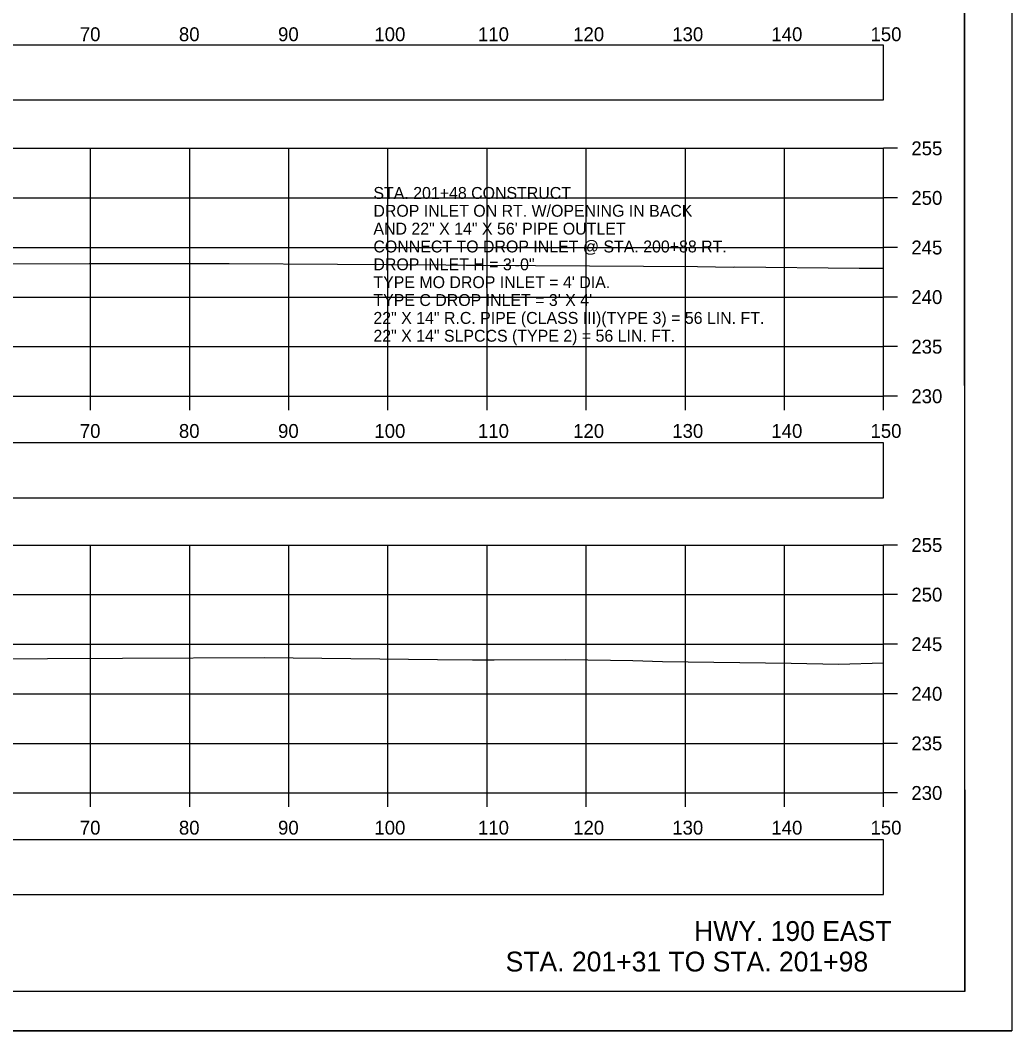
# Model space of a CAD drawing. Extents: x 1369627 to 1374022, y 380035 to 398173.
# Drawn here: x 1372161.4 to 1372261.5, y 380465.5 to 380567.3 of the extents above; entities that cross this region are included whole.
import ezdxf

# ---------------------------------------------------------------- set-up
doc = ezdxf.new("R2010")
doc.units = 0
for name, color, linetype in [('Default', 7, 'Continuous'), ('R_Axis', 7, 'Continuous'), ('R_Axis Annot', 7, 'Continuous'), ('R_Border', 7, 'Continuous'), ('R_Draft', 7, 'Continuous'), ('R_Exist Surface', 7, 'Continuous'), ('R_Grid', 7, 'Continuous'), ('R_No Plot', 7, 'Continuous'), ('R_Water Annot', 7, 'Continuous')]:
    doc.layers.add(name, color=color, linetype=linetype)

msp = doc.modelspace()

# ---------------------------------------------------------------- linework, layer by layer
at = {"layer": 'Default'}
for points in [[(1371948.53, 380559.31), (1372248.53, 380559.31), (1372248.53, 380564.83), (1371948.53, 380564.83)], [(1371948.53, 380519.2), (1372248.53, 380519.2), (1372248.53, 380524.73), (1371948.53, 380524.73)], [(1371948.53, 380479.19), (1372248.53, 380479.19), (1372248.53, 380484.71), (1371948.53, 380484.71)]]:
    msp.add_lwpolyline(points, close=True, dxfattribs=at)
at = {"layer": 'R_Axis'}
for p, q in [((1372248.53, 380529.43), (1372248.53, 380554.43)), ((1372249.93, 380554.43), (1372248.53, 380554.43)), ((1372249.93, 380549.43), (1372248.53, 380549.43)), ((1372249.93, 380544.43), (1372248.53, 380544.43)), ((1372249.93, 380539.43), (1372248.53, 380539.43)), ((1372249.93, 380534.43), (1372248.53, 380534.43)), ((1371948.53, 380529.43), (1372248.53, 380529.43)), ((1372168.53, 380528.03), (1372168.53, 380529.43)), ((1372178.53, 380528.03), (1372178.53, 380529.43)), ((1372188.53, 380528.03), (1372188.53, 380529.43)), ((1372198.53, 380528.03), (1372198.53, 380529.43)), ((1372208.53, 380528.03), (1372208.53, 380529.43)), ((1372218.53, 380528.03), (1372218.53, 380529.43)), ((1372228.53, 380528.03), (1372228.53, 380529.43)), ((1372238.53, 380528.03), (1372238.53, 380529.43)), ((1372248.53, 380528.03), (1372248.53, 380529.43)), ((1372249.93, 380529.43), (1372248.53, 380529.43)), ((1372248.53, 380489.43), (1372248.53, 380514.43)), ((1372249.93, 380514.43), (1372248.53, 380514.43)), ((1372249.93, 380509.43), (1372248.53, 380509.43)), ((1372249.93, 380504.43), (1372248.53, 380504.43)), ((1372249.93, 380499.43), (1372248.53, 380499.43)), ((1372249.93, 380494.43), (1372248.53, 380494.43)), ((1371948.53, 380489.43), (1372248.53, 380489.43)), ((1372168.53, 380488.03), (1372168.53, 380489.43)), ((1372178.53, 380488.03), (1372178.53, 380489.43)), ((1372188.53, 380488.03), (1372188.53, 380489.43)), ((1372198.53, 380488.03), (1372198.53, 380489.43)), ((1372208.53, 380488.03), (1372208.53, 380489.43)), ((1372218.53, 380488.03), (1372218.53, 380489.43)), ((1372228.53, 380488.03), (1372228.53, 380489.43)), ((1372238.53, 380488.03), (1372238.53, 380489.43)), ((1372248.53, 380488.03), (1372248.53, 380489.43)), ((1372249.93, 380489.43), (1372248.53, 380489.43))]:
    msp.add_line(p, q, dxfattribs=at)
at = {"layer": 'R_Border'}
for q in [(1372256.71, 380674.89), (1371940.53, 380469.43)]:
    msp.add_line((1372256.71, 380469.43), q, dxfattribs=at)
at = {"layer": 'R_Exist Surface'}
for points in [[(1372155.63, 380542.79), (1372168.38, 380542.8), (1372169.65, 380542.8), (1372182.51, 380542.82), (1372204.36, 380542.67), (1372206.41, 380542.64), (1372207.95, 380542.66), (1372229.75, 380542.51), (1372233.38, 380542.45), (1372233.51, 380542.47), (1372246.05, 380542.34), (1372248.53, 380542.34)], [(1372156.59, 380502.96), (1372171.75, 380503.02), (1372186.05, 380503.09), (1372203.52, 380502.89), (1372207.06, 380502.86), (1372209.25, 380502.86), (1372216.43, 380502.89), (1372223.24, 380502.79), (1372226.23, 380502.7), (1372239.21, 380502.52), (1372243.98, 380502.43), (1372248.53, 380502.54)]]:
    msp.add_lwpolyline(points, dxfattribs=at)
at = {"layer": 'R_Grid'}
for p, q in [((1371948.53, 380554.43), (1372248.53, 380554.43)), ((1372168.53, 380529.43), (1372168.53, 380554.43)), ((1372178.53, 380529.43), (1372178.53, 380554.43)), ((1372188.53, 380529.43), (1372188.53, 380554.43)), ((1372198.53, 380529.43), (1372198.53, 380554.43)), ((1372208.53, 380529.43), (1372208.53, 380554.43)), ((1372218.53, 380529.43), (1372218.53, 380554.43)), ((1372228.53, 380529.43), (1372228.53, 380554.43)), ((1372238.53, 380529.43), (1372238.53, 380554.43)), ((1372248.53, 380529.43), (1372248.53, 380554.43)), ((1371948.53, 380549.43), (1372248.53, 380549.43)), ((1371948.53, 380544.43), (1372248.53, 380544.43)), ((1371948.53, 380539.43), (1372248.53, 380539.43)), ((1371948.53, 380534.43), (1372248.53, 380534.43)), ((1371948.53, 380529.43), (1372248.53, 380529.43)), ((1371948.53, 380514.43), (1372248.53, 380514.43)), ((1372168.53, 380489.43), (1372168.53, 380514.43)), ((1372178.53, 380489.43), (1372178.53, 380514.43)), ((1372188.53, 380489.43), (1372188.53, 380514.43)), ((1372198.53, 380489.43), (1372198.53, 380514.43)), ((1372208.53, 380489.43), (1372208.53, 380514.43)), ((1372218.53, 380489.43), (1372218.53, 380514.43)), ((1372228.53, 380489.43), (1372228.53, 380514.43)), ((1372238.53, 380489.43), (1372238.53, 380514.43)), ((1372248.53, 380489.43), (1372248.53, 380514.43)), ((1371948.53, 380509.43), (1372248.53, 380509.43)), ((1371948.53, 380504.43), (1372248.53, 380504.43)), ((1371948.53, 380499.43), (1372248.53, 380499.43)), ((1371948.53, 380494.43), (1372248.53, 380494.43)), ((1371948.53, 380489.43), (1372248.53, 380489.43))]:
    msp.add_line(p, q, dxfattribs=at)
at = {"layer": 'R_No Plot'}
msp.add_line((1371928.13, 380465.46), (1372261.46, 380465.46), dxfattribs=at)
for points in [[(1371928.12, 380678.79), (1372261.46, 380678.79), (1372261.46, 380465.45), (1371928.12, 380465.45)], [(1372174.45, 380674.89), (1372194.07, 380674.89), (1372194.07, 380665.01), (1372210.18, 380665.01), (1372233.38, 380665.01), (1372233.38, 380632.34), (1372256.59, 380632.34), (1372256.71, 380469.43), (1371940.53, 380469.43), (1371940.53, 380674.89)]]:
    msp.add_lwpolyline(points, close=True, dxfattribs=at)

# ---------------------------------------------------------------- texts
at = {"layer": 'R_Axis Annot'}
for s, p in [('70', (1372167.44, 380565.23)), ('80', (1372177.44, 380565.23)), ('90', (1372187.44, 380565.23)), ('100', (1372197.16, 380565.23)), ('110', (1372207.61, 380565.23)), ('120', (1372217.21, 380565.23)), ('130', (1372227.21, 380565.23)), ('140', (1372237.21, 380565.23)), ('150', (1372247.21, 380565.23)), ('255', (1372251.33, 380553.73)), ('250', (1372251.33, 380548.73)), ('245', (1372251.33, 380543.73)), ('240', (1372251.33, 380538.73)), ('235', (1372251.33, 380533.73)), ('230', (1372251.33, 380528.73)), ('70', (1372167.44, 380525.23)), ('80', (1372177.44, 380525.23)), ('90', (1372187.44, 380525.23)), ('100', (1372197.16, 380525.23)), ('110', (1372207.61, 380525.23)), ('120', (1372217.21, 380525.23)), ('130', (1372227.21, 380525.23)), ('140', (1372237.21, 380525.23)), ('150', (1372247.21, 380525.23)), ('255', (1372251.33, 380513.73)), ('250', (1372251.33, 380508.73)), ('245', (1372251.33, 380503.73)), ('240', (1372251.33, 380498.73)), ('235', (1372251.33, 380493.73)), ('230', (1372251.33, 380488.73)), ('70', (1372167.44, 380485.23)), ('80', (1372177.44, 380485.23)), ('90', (1372187.44, 380485.23)), ('100', (1372197.16, 380485.23)), ('110', (1372207.61, 380485.23)), ('120', (1372217.21, 380485.23)), ('130', (1372227.21, 380485.23)), ('140', (1372237.21, 380485.23)), ('150', (1372247.21, 380485.23))]:
    msp.add_text(s, height=1.4, dxfattribs=at).set_placement(p)
at = {"layer": 'R_Draft'}
for s, p in [('HWY. 190 EAST', (1372229.41, 380474.51)), ('STA. 201+31 TO STA. 201+98', (1372210.4, 380471.43))]:
    msp.add_text(s, height=2, dxfattribs=at).set_placement(p)
at = {"layer": 'R_Water Annot'}
for s, p in [('STA. 201+48 CONSTRUCT', (1372197.06, 380549.33)), ('DROP INLET ON RT. W/OPENING IN BACK', (1372197.06, 380547.53)), ('AND 22" X 14" X 56\' PIPE OUTLET', (1372197.06, 380545.73)), ('CONNECT TO DROP INLET @ STA. 200+88 RT.', (1372197.06, 380543.93)), ('DROP INLET H = 3\'-0"', (1372197.06, 380542.13)), ("TYPE MO DROP INLET = 4' DIA.", (1372197.06, 380540.33)), ("TYPE C DROP INLET = 3' X 4'", (1372197.06, 380538.53)), ('22" X 14" R.C. PIPE (CLASS III)(TYPE 3) = 56 LIN. FT.', (1372197.06, 380536.73)), ('22" X 14" SLPCCS (TYPE 2) = 56 LIN. FT.', (1372197.06, 380534.93))]:
    msp.add_text(s, height=1.2, dxfattribs=at).set_placement(p)

doc.saveas('drawing.dxf')
